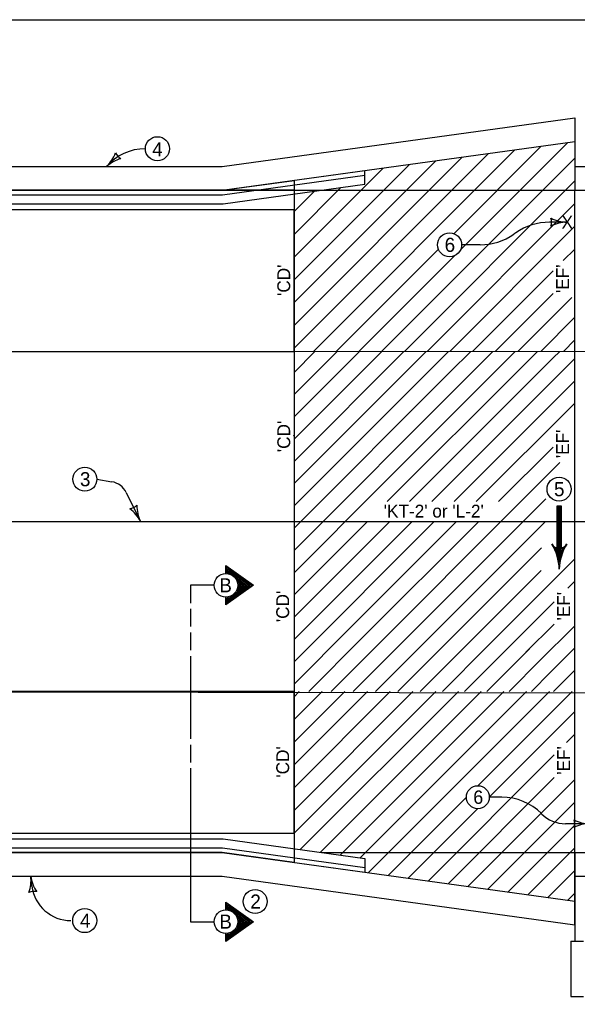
# Model space of a CAD drawing. Extents: x 9234 to 81668, y 5635 to 15999.
# Drawn here: x 22368 to 23096, y 14508 to 15800 of the extents above; entities that cross this region are included whole.
import ezdxf

# ---------------------------------------------------------------- set-up
doc = ezdxf.new("R2010")
doc.units = 0
for name, color, linetype in [('Level 61', 7, 'Continuous'), ('PS_BOLT', 7, 'Continuous'), ('PS_DIM', 7, 'Continuous'), ('PS_SHAPE', 7, 'Continuous')]:
    doc.layers.add(name, color=color, linetype=linetype)

msp = doc.modelspace()

# ---------------------------------------------------------------- linework, layer by layer
msp.add_line((22356.3, 15577.8), (23903.1, 15577.8))
at = {"layer": 'Level 61'}
msp.add_lwpolyline([(21596.3, 15800.4), (24731.3, 15800.4), (24731.3, 13780.4), (21596.3, 13780.4)], close=True, dxfattribs=at)
at = {"layer": 'PS_BOLT'}
for p, q in [((22468.8, 15200.4), (22488.3, 15197.1)), ((22507.1, 15183.1), (22525.8, 15145.3)), ((23086.1, 14943.7), (23093.3, 14951)), ((21917.1, 14923.2), (23903.1, 14920)), ((22591.2, 14822.8), (22591.2, 14622.5)), ((22997.8, 14785.1), (22981.6, 14785.1)), ((23112.4, 14750.5), (23081.1, 14750.5)), ((22384, 14668.8), (22382.4, 14681.9))]:
    msp.add_line(p, q, dxfattribs=at)
for points in [[(22622, 15061.8), (22591.2, 15061.8), (22591.2, 15038.6)], [(22591.2, 15030.9), (22591.2, 15007.8)], [(22591.2, 15000.1), (22591.2, 14977)], [(22591.2, 14969.2), (22591.2, 14861.3)], [(22591.2, 14853.6), (22591.2, 14830.5)], [(22591.2, 14634), (22591.2, 14622.5), (22622, 14622.5)]]:
    msp.add_lwpolyline(points, dxfattribs=at)
for centre, radius, start, end in [((22532.1, 15565.2), 66.8, 90, 139.4393), ((22484.1, 15171.8), 25.7, 26.2458, 80.4677), ((22997.8, 14711.7), 73.4, 45, 90), ((23081.1, 14794.6), 44.1, 225, 270), ((22435, 14675.3), 51.4, 187.2287, 270)]:
    msp.add_arc(centre, radius, start, end, dxfattribs=at)
at = {"layer": 'PS_DIM'}
for p, q in [((22943.9, 15500.1), (23084, 15640.1)), ((22726.4, 15371.6), (22980.6, 15625.8)), ((22751.8, 15367.3), (23015, 15630.6)), ((22935.2, 15521), (23049.5, 15635.4)), ((22726.4, 15401.3), (22946.1, 15621.1)), ((22726.4, 15431), (22911.7, 15616.3)), ((22726.4, 15460.7), (22877.2, 15611.6)), ((22840.9, 15367.3), (23093.3, 15619.8)), ((21980.5, 15608.6), (22393.3, 15608.6)), ((22393.3, 15608.6), (22632.6, 15608.6)), ((22632.6, 15577.8), (22818.9, 15603.5)), ((22633, 15571.6), (22818.9, 15597.3)), ((22726.4, 15490.4), (22842.8, 15606.8)), ((22818.9, 15585.6), (22818.9, 15603.5)), ((23093.3, 15608.6), (23903.1, 15608.6)), ((22633.8, 15560.1), (22818.9, 15585.6)), ((22870.6, 15367.3), (23093.3, 15590.1)), ((22066, 15577.8), (22632.6, 15577.8)), ((22066, 15571.6), (22633, 15571.6)), ((22356.3, 15577.8), (22726.4, 15577.8)), ((22726.4, 15577.8), (22356.3, 15577.8)), ((22726.4, 15520.1), (22787.5, 15581.3)), ((22726.4, 15577.8), (22726.4, 14923.2)), ((22726.4, 15549.8), (22753.1, 15576.5)), ((23093.3, 15367.3), (23093.3, 15577.8)), ((21985.8, 15560.1), (22633.8, 15560.1)), ((22900.3, 15367.3), (23093.3, 15560.4)), ((22726.4, 15552.3), (22356.3, 15552.3)), ((22726.4, 15367.3), (22726.4, 15552.3)), ((22726.4, 15367.3), (22726.4, 15552.3)), ((23093.3, 15367.3), (23093.3, 15552.3)), ((23083.1, 15536), (23060.3, 15536)), ((22930, 15367.3), (23093.3, 15530.7)), ((23016.1, 15522.1), (23013.8, 15520.5)), ((22969.6, 15506.5), (22945.4, 15506.5)), ((22781.5, 15367.3), (22915.2, 15501)), ((23078.2, 15485.8), (23093.3, 15501)), ((22811.2, 15367.3), (22936.5, 15492.6)), ((22959.7, 15367.3), (23064.9, 15472.6)), ((22989.4, 15367.3), (23064.9, 15442.9)), ((23019, 15367.3), (23089.4, 15437.6)), ((23048.7, 15367.3), (23093.3, 15411.9)), ((23078.4, 15367.3), (23093.3, 15382.2)), ((23903.1, 15366.2), (21870.4, 15367.3)), ((22356.3, 15367.3), (22726.4, 15367.3)), ((22356.3, 15367.3), (22726.4, 15367.3)), ((22726.4, 15339.9), (22753.7, 15367.3)), ((22726.4, 15310.9), (22782.8, 15367.3)), ((22726.4, 15281.8), (22811.9, 15367.3)), ((22726.4, 15252.7), (22841, 15367.3)), ((22726.4, 15223.6), (22870, 15367.3)), ((22726.4, 15194.6), (22899.1, 15367.3)), ((22726.4, 15165.5), (22928.2, 15367.3)), ((22726.4, 15367.3), (22726.4, 14923.2)), ((22931, 15341), (22957.3, 15367.3)), ((22948.4, 15329.4), (22986.3, 15367.3)), ((22974.3, 15326.2), (23015.4, 15367.3)), ((23022.7, 15345.5), (23044.5, 15367.3)), ((23065.1, 15358.8), (23073.6, 15367.3)), ((23093.3, 14923.2), (23093.3, 15367.3)), ((22877.4, 15171.1), (23065.1, 15358.8)), ((22906.4, 15171.1), (23093.3, 15358)), ((22726.4, 15136.4), (22931, 15341)), ((22848.3, 15171.1), (23022.7, 15345.5)), ((22726.4, 15107.3), (22948.4, 15329.4)), ((22839.9, 15191.8), (22974.3, 15326.2)), ((22935.5, 15171.1), (23093.3, 15329)), ((22974.3, 15326.2), (22967.5, 15319.4)), ((22964.6, 15171.1), (23093.3, 15299.9)), ((22725.9, 15257.4), (22726.4, 15257.8)), ((22993.7, 15171.1), (23064.9, 15242.4)), ((22774.9, 14923.2), (23073.6, 15222)), ((22726.4, 15078.3), (22839.9, 15191.8)), ((22803.9, 14923.2), (23055.6, 15174.9)), ((23073, 15110.6), (23073, 15165.1)), ((22356.3, 15145.3), (24237.5, 15145.3)), ((22726.4, 15049.2), (22822.5, 15145.3)), ((22726.4, 15020.1), (22851.5, 15145.3)), ((22726.4, 14991), (22880.6, 15145.3)), ((22726.4, 14962), (22909.7, 15145.3)), ((22800.7, 15007.2), (22938.8, 15145.3)), ((22815.2, 14992.7), (22967.8, 15145.3)), ((22833, 14923.2), (23055.1, 15145.3)), ((22862.1, 14923.2), (23049.6, 15110.8)), ((23069.9, 15110.7), (23069.9, 15110.7)), ((23076.3, 15110.8), (23076.3, 15110.8)), ((22978.5, 14981.5), (23093.3, 15096.4)), ((22962.1, 14994.1), (23049.2, 15081.3)), ((23084.3, 15058.2), (23093.3, 15067.3)), ((23007, 14980.9), (23066.2, 15040.1)), ((22726.4, 14932.9), (22800.7, 15007.2)), ((23029.5, 14974.4), (23066.2, 15011)), ((23046, 14961.7), (23093.3, 15009.1)), ((22745.8, 14923.2), (22815.2, 14992.7)), ((22891.2, 14923.2), (22966.2, 14998.2)), ((22920.2, 14923.2), (22978.5, 14981.5)), ((22949.3, 14923.2), (23007, 14980.9)), ((22978.4, 14923.2), (23033.9, 14978.8)), ((23061.5, 14948.2), (23093.3, 14980.1)), ((23007.5, 14923.2), (23049.1, 14964.9)), ((23036.5, 14923.2), (23061.5, 14948.2)), ((23065.6, 14923.2), (23086.1, 14943.7)), ((22726.4, 14923.2), (22356.3, 14923.2)), ((22726.4, 14923.2), (22356.3, 14923.2)), ((22726.4, 14923.2), (22726.4, 14738.2)), ((22726.4, 14923.2), (22726.4, 14699.8)), ((22726.4, 14738.2), (22911.5, 14923.2)), ((22726.4, 14767.8), (22881.8, 14923.2)), ((22726.4, 14797.5), (22852.1, 14923.2)), ((22726.4, 14856.9), (22792.7, 14923.2)), ((22726.4, 14886.6), (22763, 14923.2)), ((22726.4, 14916.3), (22733.3, 14923.2)), ((22726.4, 14827.2), (22822.4, 14923.2)), ((22726.4, 14738.2), (22726.4, 14923.2)), ((22734.5, 14716.6), (22941.2, 14923.2)), ((22760.6, 14713), (22970.9, 14923.2)), ((22786.7, 14709.4), (23000.6, 14923.2)), ((22812.8, 14705.8), (23030.3, 14923.2)), ((22823.2, 14686.5), (23060, 14923.2)), ((22966.6, 14800.1), (23089.7, 14923.2)), ((23093.3, 14712.8), (23093.3, 14923.2)), ((22981.4, 14785.3), (23093.3, 14897.2)), ((23082.5, 14856.7), (23093.3, 14867.5)), ((22901.5, 14675.6), (23066.2, 14840.4)), ((22927.6, 14672), (23066.2, 14810.7)), ((22953.6, 14668.4), (23093.3, 14808.1)), ((22849.3, 14682.9), (22951.7, 14785.3)), ((22875.4, 14679.2), (22966.6, 14770.5)), ((22979.7, 14664.8), (23093.3, 14778.4)), ((23005.8, 14661.2), (23093.3, 14748.7)), ((22356.3, 14738.2), (22726.4, 14738.2)), ((21985.8, 14730.5), (22633.8, 14730.5)), ((22066, 14718.9), (22633, 14718.9)), ((22633, 14718.9), (22818.9, 14693.3)), ((22633.8, 14730.5), (22818.9, 14704.9)), ((23031.9, 14657.6), (23093.3, 14719)), ((22066, 14712.8), (22632.6, 14712.8)), ((22632.6, 14712.8), (22818.9, 14687)), ((22762.2, 14712.8), (23903.1, 14712.8)), ((23093.3, 14712.8), (23093.3, 14597.1)), ((22818.9, 14704.9), (22818.9, 14687)), ((22066, 14681.9), (22393.3, 14681.9)), ((22393.3, 14681.9), (22632.6, 14681.9)), ((23058, 14654), (23093.3, 14689.3)), ((23093.3, 14681.9), (23903.1, 14681.9)), ((23084.1, 14650.4), (23093.3, 14659.6)), ((23088.2, 14597.1), (23104.7, 14597.1)), ((23088.2, 14597.1), (23088.2, 14524.6)), ((23088.2, 14524.6), (23104.7, 14524.6))]:
    msp.add_line(p, q, dxfattribs=at)
for points in [[(22632.6, 15608.6), (23093.3, 15672.3), (23093.3, 15641.4)], [(23093.3, 15367.3), (23093.3, 15367.3)], [(23076, 15110.7), (23076, 15165.1), (23069.9, 15165.1), (23069.9, 15110.7), (23075.2, 15110.9), (23075.4, 15164.4), (23070.5, 15164.3), (23070.7, 15111.9), (23074.3, 15111.8), (23074.5, 15163.7), (23071.3, 15163.5), (23071.3, 15112.6), (23073.6, 15112.4), (23073.9, 15163.1), (23072, 15163), (23072.1, 15113.3)], [(23080.1, 15112.2), (23076.4, 15109.9), (23071, 15109.6), (23066.3, 15111.6), (23069.6, 15103.5), (23072.4, 15094.1), (23073, 15091.5), (23074.3, 15098.3), (23077.7, 15108.2), (23079.3, 15111.1), (23067.9, 15110), (23072.8, 15095.5), (23077.1, 15109.7), (23069.2, 15109.1), (23072.8, 15099.2), (23075.1, 15108.3), (23070.5, 15108.7), (23072.6, 15102.4), (23073.9, 15107.2), (23071.7, 15107.5), (23072.4, 15105.2)], [(22637.4, 15077.2), (22637.4, 15087.5), (22673.4, 15061.8), (22637.4, 15036.1), (22637.4, 15046.3)], [(22638.4, 15045.3), (22638.4, 15037.9), (22671.5, 15061.8), (22638.3, 15085.8), (22638.5, 15077.9), (22639.9, 15077.5), (22639.4, 15083.3), (22669.3, 15061.8), (22639.4, 15040), (22639.7, 15045.5), (22640.8, 15045.7), (22640.7, 15042.1), (22667.3, 15061.8), (22640.6, 15080.6), (22641.1, 15077.4), (22642.3, 15077.1), (22642.2, 15078.2), (22665, 15061.5), (22641.8, 15044), (22642.9, 15046), (22663, 15061.4), (22650.7, 15071.2), (22651.5, 15069.4), (22660.9, 15061.3), (22651.8, 15054.3), (22652.6, 15056.2), (22659, 15061.1), (22652.6, 15066.6), (22653.2, 15064.2), (22657.4, 15061), (22653.2, 15057.7), (22653.4, 15059.4), (22655.8, 15060.9), (22653.5, 15062.3), (22653.6, 15060.8), (22654.4, 15060.9)], [(23093.3, 14923.2), (23093.3, 14923.2)], [(22632.6, 14681.9), (23093.3, 14618.3), (23093.3, 14649.1)], [(22637.4, 14638), (22637.4, 14648.2), (22673.4, 14622.5), (22637.4, 14596.8), (22637.4, 14607.1)], [(22638.4, 14606.1), (22638.4, 14598.7), (22671.5, 14622.6), (22638.3, 14646.6), (22638.5, 14638.7), (22639.9, 14638.3), (22639.4, 14644), (22669.3, 14622.6), (22639.4, 14600.8), (22639.7, 14606.3), (22640.8, 14606.5), (22640.7, 14602.9), (22667.3, 14622.6), (22640.6, 14641.4), (22641.1, 14638.2), (22642.3, 14637.9), (22642.2, 14639), (22665, 14622.3), (22641.8, 14604.8), (22642.9, 14606.7), (22663, 14622.2), (22650.7, 14631.9), (22651.5, 14630.2), (22660.9, 14622.1), (22651.8, 14615.1), (22652.6, 14617), (22659, 14621.9), (22652.6, 14627.4), (22653.2, 14625), (22657.4, 14621.8), (22653.2, 14618.5), (22653.4, 14620.2), (22655.8, 14621.7), (22653.5, 14623.1), (22653.6, 14621.6), (22654.4, 14621.7)]]:
    msp.add_lwpolyline(points, dxfattribs=at)
for points in [[(22356.3, 15560.1), (22356.3, 15560.1), (22356.3, 15577.8), (22632.6, 15577.8), (22726.4, 15590.7), (22726.4, 15552.3), (22356.3, 15552.3)], [(22356.3, 14712.8), (22356.3, 14738.2), (22726.4, 14738.2), (22726.4, 14699.8), (22632.6, 14712.8), (22356.3, 14712.8)]]:
    msp.add_lwpolyline(points, close=True, dxfattribs=at)
for centre, radius in [((22547.9, 15632), 15.7), ((22929.7, 15506.5), 15.7), ((22453.1, 15200.4), 15.7), ((23072.7, 15187.4), 15.7), ((22637.4, 15061.8), 15.4), ((22966.6, 14785.1), 15), ((22675.6, 14648.8), 15.7), ((22452.9, 14623.9), 15.7), ((22637.4, 14622.5), 15.4)]:
    msp.add_circle(centre, radius, dxfattribs=at)
for centre, radius, start, end in [((22451.2, 15641.2), 44.4, 312.7719, 340.8444), ((22508.7, 15633.9), 17.1, 205.0386, 240.5053), ((22511.5, 15576), 44.4, 104.6994, 132.7719), ((23060.3, 15458.9), 77.1, 90, 124.9993), ((23045.8, 15536), 17.1, 342.2666, 17.7334), ((23083.1, 15580.4), 44.4, 241.9275, 270), ((23045.9, 15536), 17.1, 342.2666, 17.7334), ((23083.1, 15580.4), 44.4, 241.9275, 270), ((23083.1, 15491.6), 44.4, 90, 118.0725), ((23083.1, 15491.6), 44.4, 90, 118.0725), ((22969.6, 15583.6), 77.1, 270, 304.9999), ((22509.3, 15178.7), 17.1, 278.5122, 313.9789), ((22486, 15125.7), 44.4, 26.2455, 54.318), ((22565.6, 15164.9), 44.4, 178.1731, 206.2455), ((23073, 15121.9), 11.6, 211.7147, 328.2853), ((23006.7, 15080.9), 66.3, 1.6842, 31.7143), ((23139.2, 15080.9), 66.3, 148.2857, 178.3158), ((23076.9, 14750.5), 16.3, 342.2666, 17.7333), ((23112.4, 14792.8), 42.3, 241.9275, 270), ((23112.4, 14708.3), 42.3, 90, 118.0725), ((22338.4, 14676.3), 44.4, 339.1562, 7.2287), ((22426.4, 14687.5), 44.4, 187.2287, 215.3012), ((22387.1, 14645), 17.1, 79.4954, 114.9621)]:
    msp.add_arc(centre, radius, start, end, dxfattribs=at)
at = {"layer": 'PS_SHAPE'}
for points in [[(22632.6, 15577.8), (23093.3, 15641.4), (23093.3, 15577.8)], [(22632.6, 14712.8), (23093.3, 14649.1), (23093.3, 14712.8)]]:
    msp.add_lwpolyline(points, dxfattribs=at)

# ---------------------------------------------------------------- texts
at = {"layer": 'PS_BOLT'}
for s, height, p in [('4', 18.4, (22541.1, 15622.1)), ('X', 16.8, (23075.9, 15527.6)), ('6', 18.4, (22923.2, 15497.3)), ('3', 18.4, (22446.7, 15191.2)), ('5', 18.4, (23066.1, 15178.2)), ("'KT-2' or 'L-2'", 16.8, (22843.6, 15150.3)), ('B', 18.4, (22628.8, 15052.6)), ('6', 17.5, (22960.6, 14776.4)), ('2', 18.4, (22669.3, 14639.6)), ('4', 18.4, (22446.8, 14614.7)), ('B', 18.4, (22628.8, 14613.4))]:
    msp.add_text(s, height=height, dxfattribs=at).set_placement(p)
for s, p in [("'CD'", (22721.4, 15439.7)), ("'EF'", (23085.7, 15443.5)), ("'CD'", (22721.4, 15235.7)), ("'EF'", (23085.7, 15227.9)), ("'CD'", (22720, 15013.7)), ("'EF'", (23087, 15015.9)), ("'CD'", (22720, 14810.6)), ("'EF'", (23087, 14814.4))]:
    msp.add_text(s, height=16.8, rotation=90, dxfattribs=at).set_placement(p)

doc.saveas('drawing.dxf')
